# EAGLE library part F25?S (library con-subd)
SUB-D
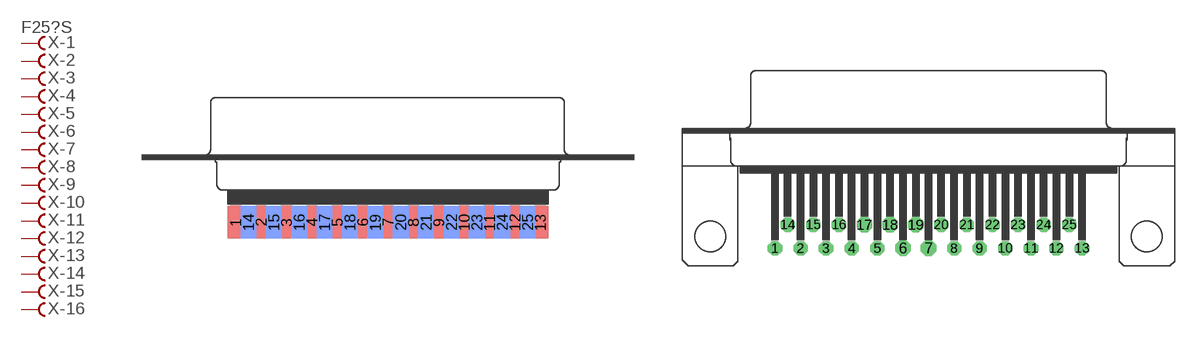
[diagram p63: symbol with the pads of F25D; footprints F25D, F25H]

Designator prefix X; gates -1=FV -2=F -3=F -4=F -5=F -6=F -7=F -8=F -9=F -10=F -11=F -12=F -13=F -14=F -15=F -16=F -17=F -18=F -19=F -20=F -21=F -22=F -23=F -24=F -25=F

## F25DS (OC_FARNELL: unknown; OC_NEWARK: unknown)  [F25D]
1  -1:F  pas
2  -2:F  pas
3  -3:F  pas
4  -4:F  pas
5  -5:F  pas
6  -6:F  pas
7  -7:F  pas
8  -8:F  pas
9  -9:F  pas
10  -10:F  pas
11  -11:F  pas
12  -12:F  pas
13  -13:F  pas
14  -14:F  pas
15  -15:F  pas
16  -16:F  pas
17  -17:F  pas
18  -18:F  pas
19  -19:F  pas
20  -20:F  pas
21  -21:F  pas
22  -22:F  pas
23  -23:F  pas
24  -24:F  pas
25  -25:F  pas

## F25HS (OC_FARNELL: unknown; OC_NEWARK: unknown)  [F25H]
Pads as for F25D

## F25HPS (OC_FARNELL: unknown; OC_NEWARK: unknown)  [F25HP]
Pads as for F25D

## F25VS (OC_FARNELL: unknown; OC_NEWARK: unknown)  [F25V]
Pads as for F25D

## F25VPS (OC_FARNELL: unknown; OC_NEWARK: unknown)  [F25VP]
Pads as for F25D

## F25VBS (OC_FARNELL: unknown; OC_NEWARK: unknown)  [F25VB]
Pads as for F25D

## F25.590S (OC_FARNELL: unknown; OC_NEWARK: unknown)  [177-025-FEMALE]
Pads as for F25D

## Footprint F25D (pad centres in mm)
SUB-D
smd 1.7 x 3.5: 1 -16.459,-6.045; 2 -13.716,-6.045; 3 -10.973,-6.045; 4 -8.23,-6.045; 5 -5.486,-6.045; 6 -2.743,-6.045; 7 0,-6.045; 8 2.743,-6.045; 9 5.486,-6.045; 10 8.23,-6.045; 11 10.973,-6.045; 12 13.716,-6.045; 13 16.459,-6.045
smd 1.7 x 3.5 bottom: 14 -15.088,-6.045; 15 -12.344,-6.045; 16 -9.601,-6.045; 17 -6.858,-6.045; 18 -4.115,-6.045; 19 -1.372,-6.045; 20 1.372,-6.045; 21 4.115,-6.045; 22 6.858,-6.045; 23 9.601,-6.045; 24 12.344,-6.045; 25 15.088,-6.045

## Footprint F25H (pad centres in mm)
SUB-D
drill 1.016 octagon: 1 -16.561,-1.27; 2 -13.792,-1.27; 3 -11.049,-1.27; 4 -8.28,-1.27; 5 -5.512,-1.27; 8 2.769,-1.27; 9 5.512,-1.27; 10 8.28,-1.27; 11 11.049,-1.27; 12 13.792,-1.27; 13 16.561,-1.27; 14 -15.189,1.27; 15 -12.421,1.27; 16 -9.652,1.27; 20 1.372,1.27; 21 4.14,1.27; 22 6.909,1.27; 23 9.652,1.27; 24 12.421,1.27; 25 15.189,1.27
drill 1.016 pad 1.67 octagon: 6 -2.769,-1.27; 7 0,-1.27; 17 -6.909,1.27; 18 -4.14,1.27; 19 -1.372,1.27
hole 3.302 at -23.52,0
hole 3.302 at 23.52,0

## Footprint F25HP (pad centres in mm)
SUB-D
drill 1.016 octagon: 1 -16.561,-1.27; 2 -13.792,-1.27; 3 -11.049,-1.27; 4 -8.28,-1.27; 5 -5.512,-1.27; 6 -2.769,-1.27; 7 0,-1.27; 8 2.769,-1.27; 9 5.512,-1.27; 10 8.28,-1.27; 11 11.049,-1.27; 12 13.792,-1.27; 13 16.561,-1.27; 14 -15.189,1.27; 15 -12.421,1.27; 16 -9.652,1.27; 17 -6.909,1.27; 18 -4.14,1.27; 19 -1.372,1.27; 20 1.372,1.27; 21 4.14,1.27; 22 6.909,1.27; 23 9.652,1.27; 24 12.421,1.27; 25 15.189,1.27
drill 3.302 pad 5.08 round: G1 -23.52,0; G2 23.52,0

## Footprint F25V (pad centres in mm)
SUB-D
drill 1.016 octagon: 1 16.561,1.422; 2 13.792,1.422; 3 11.049,1.422; 4 8.28,1.422; 5 5.512,1.422; 6 2.769,1.422; 7 0,1.422; 8 -2.769,1.422; 9 -5.512,1.422; 10 -8.28,1.422; 11 -11.049,1.422; 12 -13.792,1.422; 13 -16.561,1.422; 14 15.189,-1.422; 15 12.421,-1.422; 16 9.652,-1.422; 17 6.909,-1.422; 18 4.14,-1.422; 19 1.372,-1.422; 20 -1.372,-1.422; 21 -4.14,-1.422; 22 -6.909,-1.422; 23 -9.652,-1.422; 24 -12.421,-1.422; 25 -15.189,-1.422
hole 3.302 at 23.52,0
hole 3.302 at -23.52,0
